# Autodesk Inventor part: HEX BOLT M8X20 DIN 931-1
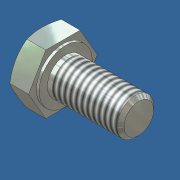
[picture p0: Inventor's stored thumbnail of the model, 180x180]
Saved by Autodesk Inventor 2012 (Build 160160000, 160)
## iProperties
Created: 2006-02
Part Number: HEX BOLT M8X20 DIN 931-1
Material: Steel, Mild
Description: Hex-Head Bolt
Document SubType Name: Modeling
Standard: DIN 931-1
Designer: Andy Moles
Standards Organization: DIN
Language: en-US
Size Designation: M8 x 35
Categories: <MemberInstance><Categories><Category DisplayName="Fasteners" InternalName="e4da775c-781d-43d5-af7c-5136215cf5a6" Mnemonic="FSTN"><Category DisplayName="Bolts"
Density: 7.86 g/cm^3
Mass: 13.7339 g
Surface Area: 10.0998 cm^2
Volume: 1.74731 cm^3
Author: Andy Moles
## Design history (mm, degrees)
workplane "Work Plane1"
revolve "Body" stored, may be unused: angle "d12" = 90 deg
sketch "Sketch2"
  geometry: L1 (0, 7.506)-(6.5, 3.753); L2 (6.5, 3.753)-(6.5, -3.753); L3 (6.5, -3.753)-(0, -7.506); L4 (0, -7.506)-(-6.5, -3.753); L5 (-6.5, -3.753)-(-6.5, 3.753); L6 (-6.5, 3.753)-(0, 7.506); 2 further points
  constraints: 12 end point, 1 coincident, 1 vertical, 11 other
  dimensions: "d11" = 13 distance between parallel lines of L5 L2 (= SW)
extrude "Head" join sketch "Sketch2" distance "d3" = 4.7 (= KOH - SD); taper "d4" = 0 deg
revolve "Chamfer1" stored, may be unused: angle "d21" = 90 deg
body "Solid1"
feature "Thread" dims "d15" = 19 (= GEL), "d16" = 0
chamfer "Chamfer2" distance "d6" = 0.76681 (= -0.5 x SPD + 0.5 x GD); stored, may be unused: second distance "d7" = 0.76691 (computed from GUL), angle "d55" = 45 deg
sketch "Sketch1"
  geometry: L1 (0, 5.8)-(0, 4); L2 (1, 4)-(20, 4); L3 (20, 4)-(20, 0); L4 (20, 0)-(-0.6, 0); L5 (-2.26, 0)-(20.98, 0) reference; L6 (-0.6, 0)-(-0.6, 5.8); L7 (-0.6, 5.8)-(0, 5.8); L8 (1, 4)-(0.233, 4); L9 (0.233, 4)-(0, 4); L10 (0, -0.58)-(0, 7.54) reference
  constraints: 16 end point, 2 collinear, 2 perpendicular, 1 parallel
  dimensions: "d0" = 20 distance between parallel lines of L3 L1 (= NLG); "d1" = 19 distance from line of L2.start L3 (= GEL); "d2" = 8 diameter of L2 L4 (= GD); "d9" = 0.6001 distance between parallel lines of L6 L1 (computed from SD); "d10" = 11.6 diameter of L7 L4 (= SD2); "d13" = 0.76691 distance of L2.start L8.end (computed from GAL); "d14" = 8 diameter of L9 L4 (= BDM)
sketch "Sketch4"
  geometry: L1 (-5.3, 6.5)-(-5.3, 7.506); L2 (-5.3, 7.506)-(-4.72, 7.506); L3 (-4.72, 7.506)-(-5.3, 6.5); L4 (-5.77, 0)-(0.81, 0) reference; L5 (-0.6, 7.506)-(-5.3, 7.506) reference; L6 (-5.3, 3.753)-(-5.3, 7.506) reference
  constraints: 6 end point, 2 collinear, 1 perpendicular, 1 vertical
  dimensions: "d5" = 30 deg angle of L3 L1 (= ANG1); "d19" = 13 diameter of L1.start L4 (= SW0)
other parameters: "NLG" = 20 [user parameter; used in 1 equation term], "GD" = 8 (= NND) [user parameter; used in 2 equation terms], "BDM" = 8 (= NND) [user parameter; used in 1 equation term], "KOH" = 5.3 [user parameter; used in 1 equation term], "GEL" = 19 [user parameter; used in 2 equation terms], "SW" = 13 [user parameter; used in 3 equation terms], "SW0" = 13 (= SW) [user parameter; used in 1 equation term], "SPD" = 6.46637 (= NND - 1.2269 x PTC) [user parameter; used in 1 equation term], "SD2" = 11.6 [user parameter; used in 1 equation term], "SD" = 0.6 [user parameter; used in 2 equation terms], "ANG1" = 30 deg [user parameter; used in 1 equation term], "GAL" = 0.76681 (= 0.61345 x PTC) [user parameter; used in 1 equation term], "GUL" = 0.76681 (= 0.61345 x PTC) [user parameter; used in 1 equation term], "d8" = 0, "RR" = 0.4 [user parameter], "d57" = 0, "d58" = 0, "TPU" = 8 (computed from PTC) [user parameter], "GD1" = 6.46637 (= THREADDIA - 1.2269 x PTC) [user parameter], "THREADDIA" = 8 [user parameter; used in 1 equation term], "TOA" = 30 deg [user parameter], "PTC" = 1.25 [user parameter; used in 5 equation terms], "NND" = 8 [user parameter; used in 3 equation terms], "E0" = 15.015 (= 1.155 x SW) [user parameter]
